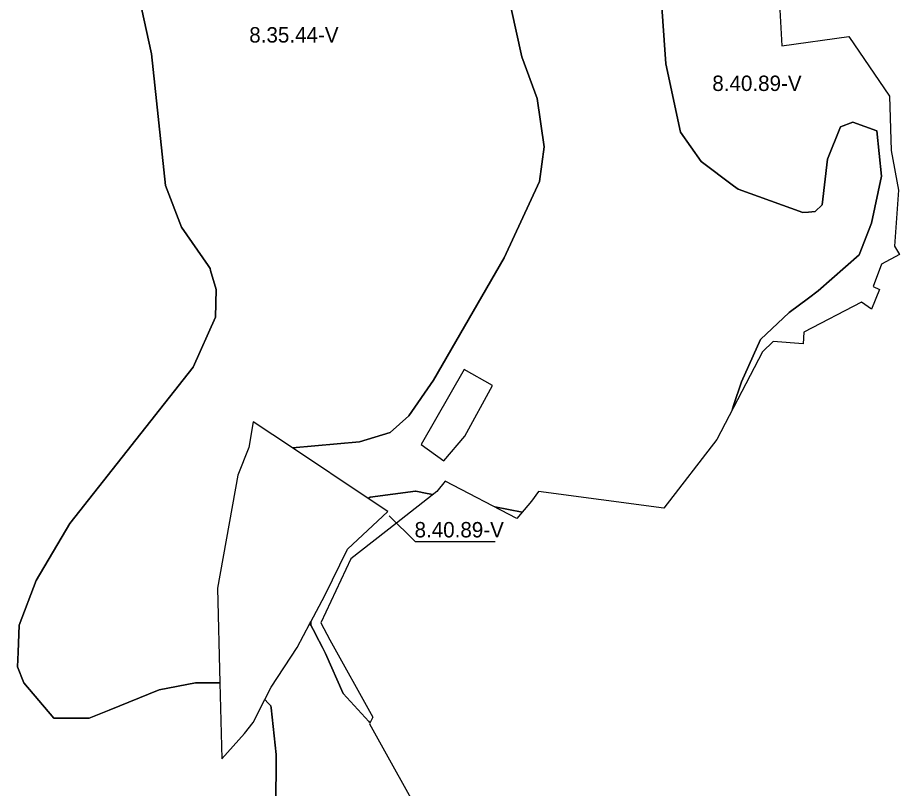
# Model space of a CAD drawing. Extents: x -547623 to -533936, y -1096714 to -1086523.
# Drawn here: x -544544 to -543971, y -1095788 to -1095288 of the extents above; entities that cross this region are included whole.
import ezdxf

# ---------------------------------------------------------------- set-up
doc = ezdxf.new("R2010")
doc.units = 0
doc.layers.add('Vrstva 27', color=7, linetype='Continuous')
doc.layers.add('Vrstva 28', color=7, linetype='Continuous')

msp = doc.modelspace()

# ---------------------------------------------------------------- linework, layer by layer
at = {"layer": 'Vrstva 27'}
msp.add_lwpolyline([(-544302.77, -1095610.93), (-544285.93, -1095627.77), (-544233.93, -1095627.77)], dxfattribs=at)
at = {"layer": 'Vrstva 28'}
for p, q in [((-544128, -1095246), (-544123, -1095317.5)), ((-544123, -1095317.5), (-544128, -1095246)), ((-544468, -1095261.5), (-544457, -1095311)), ((-544457, -1095311), (-544468, -1095261.5)), ((-544223.5, -1095281.5), (-544216.5, -1095313)), ((-544216.5, -1095313), (-544223.5, -1095281.5)), ((-544457, -1095311), (-544448, -1095396.5)), ((-544448, -1095396.5), (-544457, -1095311)), ((-544216.5, -1095313), (-544206.5, -1095340)), ((-544206.5, -1095340), (-544216.5, -1095313)), ((-544123, -1095317.5), (-544113.5, -1095362)), ((-544113.5, -1095362), (-544123, -1095317.5)), ((-544206.5, -1095340), (-544202, -1095371.5)), ((-544202, -1095371.5), (-544206.5, -1095340)), ((-544018, -1095379.5), (-544009.5, -1095358.5)), ((-544009.5, -1095358.5), (-544018, -1095379.5)), ((-544009.5, -1095358.5), (-544001.5, -1095355.5)), ((-544001.5, -1095355.5), (-544009.5, -1095358.5)), ((-544001.5, -1095355.5), (-543986, -1095361)), ((-543986, -1095361), (-544001.5, -1095355.5)), ((-543986, -1095361), (-543983, -1095390.5)), ((-543983, -1095390.5), (-543986, -1095361)), ((-544113.5, -1095362), (-544100, -1095381)), ((-544100, -1095381), (-544113.5, -1095362)), ((-544202, -1095371.5), (-544205, -1095394)), ((-544205, -1095394), (-544202, -1095371.5)), ((-544100, -1095381), (-544079.02, -1095396.73)), ((-544079.02, -1095396.73), (-544100, -1095381)), ((-544021.5, -1095409), (-544018, -1095379.5)), ((-544018, -1095379.5), (-544021.5, -1095409)), ((-544205, -1095394), (-544228, -1095443.5)), ((-544228, -1095443.5), (-544205, -1095394)), ((-543983, -1095390.5), (-543989.5, -1095421)), ((-543989.5, -1095421), (-543983, -1095390.5)), ((-544448, -1095396.5), (-544437.5, -1095423.5)), ((-544437.5, -1095423.5), (-544448, -1095396.5)), ((-544079.02, -1095396.73), (-544076, -1095399)), ((-544076, -1095399), (-544079.02, -1095396.73)), ((-544076, -1095399), (-544034, -1095414)), ((-544034, -1095414), (-544076, -1095399)), ((-544026, -1095413.5), (-544021.5, -1095409)), ((-544021.5, -1095409), (-544026, -1095413.5)), ((-544034, -1095414), (-544030.47, -1095413.78)), ((-544030.47, -1095413.78), (-544034, -1095414)), ((-544030.47, -1095413.78), (-544026, -1095413.5)), ((-544026, -1095413.5), (-544030.47, -1095413.78)), ((-544437.5, -1095423.5), (-544420.35, -1095448.53)), ((-544420.35, -1095448.53), (-544437.5, -1095423.5)), ((-543989.5, -1095421), (-543997.5, -1095441.5)), ((-543997.5, -1095441.5), (-543989.5, -1095421)), ((-544228, -1095443.5), (-544274, -1095523)), ((-544274, -1095523), (-544228, -1095443.5)), ((-543997.5, -1095441.5), (-544024, -1095465)), ((-544024, -1095465), (-543997.5, -1095441.5)), ((-544420.35, -1095448.53), (-544419, -1095450.5)), ((-544419, -1095450.5), (-544420.35, -1095448.53)), ((-544419, -1095450.5), (-544418.64, -1095451.72)), ((-544418.64, -1095451.72), (-544419, -1095450.5)), ((-544418.64, -1095451.72), (-544415, -1095464)), ((-544415, -1095464), (-544418.64, -1095451.72)), ((-544415, -1095464), (-544415.5, -1095482)), ((-544415.5, -1095482), (-544415, -1095464)), ((-544030.47, -1095469.77), (-544043, -1095479)), ((-544043, -1095479), (-544030.47, -1095469.77)), ((-544024, -1095465), (-544030.47, -1095469.77)), ((-544030.47, -1095469.77), (-544024, -1095465)), ((-544043, -1095479), (-544061.5, -1095496.5)), ((-544061.5, -1095496.5), (-544043, -1095479)), ((-544415.5, -1095482), (-544430, -1095514.5)), ((-544430, -1095514.5), (-544415.5, -1095482)), ((-544061.5, -1095496.5), (-544074, -1095524)), ((-544074, -1095524), (-544061.5, -1095496.5)), ((-544430, -1095514.5), (-544510, -1095616)), ((-544510, -1095616), (-544430, -1095514.5)), ((-544274, -1095523), (-544290, -1095546)), ((-544290, -1095546), (-544274, -1095523)), ((-544074, -1095524), (-544079.02, -1095539.28)), ((-544079.02, -1095539.28), (-544074, -1095524)), ((-544079.02, -1095539.28), (-544080.03, -1095542.35)), ((-544080.03, -1095542.35), (-544079.02, -1095539.28)), ((-544080.03, -1095542.35), (-544080.03, -1095542.35)), ((-544080.03, -1095542.35), (-544080.03, -1095542.35)), ((-544290, -1095546), (-544302, -1095557)), ((-544302, -1095557), (-544290, -1095546)), ((-544302, -1095557), (-544322, -1095563)), ((-544322, -1095563), (-544302, -1095557)), ((-544322, -1095563), (-544365.6, -1095566.9)), ((-544365.6, -1095566.9), (-544322, -1095563)), ((-544365.6, -1095566.9), (-544365.6, -1095566.9)), ((-544365.6, -1095566.9), (-544365.6, -1095566.9)), ((-544285.69, -1095595.02), (-544315, -1095599)), ((-544315, -1095599), (-544285.69, -1095595.02)), ((-544285.5, -1095595), (-544285.69, -1095595.02)), ((-544285.69, -1095595.02), (-544285.5, -1095595)), ((-544278.04, -1095596.48), (-544285.5, -1095595)), ((-544285.5, -1095595), (-544278.04, -1095596.48)), ((-544316.32, -1095599.68), (-544316.33, -1095599.68)), ((-544316.33, -1095599.68), (-544316.32, -1095599.68)), ((-544315, -1095599), (-544316.32, -1095599.68)), ((-544316.32, -1095599.68), (-544315, -1095599)), ((-544274.31, -1095597.23), (-544278.04, -1095596.48)), ((-544278.04, -1095596.48), (-544274.31, -1095597.23)), ((-544274.31, -1095597.23), (-544274.31, -1095597.23)), ((-544274.31, -1095597.23), (-544274.31, -1095597.23)), ((-544216.41, -1095608.74), (-544234.07, -1095605.23)), ((-544234.07, -1095605.23), (-544216.41, -1095608.74)), ((-544234.07, -1095605.23), (-544234.07, -1095605.23)), ((-544234.07, -1095605.23), (-544234.07, -1095605.23)), ((-544216.41, -1095608.74), (-544216.41, -1095608.74)), ((-544216.41, -1095608.74), (-544216.41, -1095608.74)), ((-544510, -1095616), (-544532, -1095653)), ((-544532, -1095653), (-544510, -1095616)), ((-544532, -1095653), (-544543, -1095682)), ((-544543, -1095682), (-544532, -1095653)), ((-544354.2, -1095680.99), (-544353.5, -1095682)), ((-544353.5, -1095682), (-544354.2, -1095680.99)), ((-544353.59, -1095679.84), (-544353.5, -1095682)), ((-544353.5, -1095682), (-544353.59, -1095679.84)), ((-544543, -1095682), (-544543.65, -1095699.52)), ((-544543.65, -1095699.52), (-544543, -1095682)), ((-544353.5, -1095682), (-544352.01, -1095684.91)), ((-544352.01, -1095684.91), (-544353.5, -1095682)), ((-544352.01, -1095684.91), (-544351.88, -1095685.16)), ((-544351.88, -1095685.16), (-544352.01, -1095684.91)), ((-544351.88, -1095685.16), (-544350.53, -1095687.79)), ((-544350.53, -1095687.79), (-544351.88, -1095685.16)), ((-544350.53, -1095687.79), (-544345.99, -1095696.62)), ((-544345.99, -1095696.62), (-544350.53, -1095687.79)), ((-544345.99, -1095696.62), (-544344, -1095700.5)), ((-544344, -1095700.5), (-544345.99, -1095696.62)), ((-544543.65, -1095699.52), (-544544, -1095709)), ((-544544, -1095709), (-544543.65, -1095699.52)), ((-544344, -1095700.5), (-544332.5, -1095726.5)), ((-544332.5, -1095726.5), (-544344, -1095700.5)), ((-544544, -1095709), (-544540, -1095719.5)), ((-544540, -1095719.5), (-544544, -1095709)), ((-544540, -1095719.5), (-544520.5, -1095742.5)), ((-544520.5, -1095742.5), (-544540, -1095719.5)), ((-544452, -1095724), (-544428.5, -1095719.5)), ((-544428.5, -1095719.5), (-544452, -1095724)), ((-544428.5, -1095719.5), (-544418.73, -1095719.5)), ((-544418.73, -1095719.5), (-544428.5, -1095719.5)), ((-544418.73, -1095719.5), (-544412.68, -1095719.5)), ((-544412.68, -1095719.5), (-544418.73, -1095719.5)), ((-544484.65, -1095737.27), (-544452, -1095724)), ((-544452, -1095724), (-544484.65, -1095737.27)), ((-544332.5, -1095726.5), (-544316, -1095744.5)), ((-544316, -1095744.5), (-544332.5, -1095726.5)), ((-544383.41, -1095730.33), (-544381.22, -1095732.66)), ((-544381.22, -1095732.66), (-544383.41, -1095730.33)), ((-544381.22, -1095732.66), (-544379.5, -1095734.5)), ((-544379.5, -1095734.5), (-544381.22, -1095732.66)), ((-544497.5, -1095742.5), (-544484.65, -1095737.27)), ((-544484.65, -1095737.27), (-544497.5, -1095742.5)), ((-544379.5, -1095734.5), (-544379.38, -1095735.61)), ((-544379.38, -1095735.61), (-544379.5, -1095734.5)), ((-544379.38, -1095735.61), (-544376, -1095766)), ((-544376, -1095766), (-544379.38, -1095735.61)), ((-544520.5, -1095742.5), (-544497.5, -1095742.5)), ((-544497.5, -1095742.5), (-544520.5, -1095742.5)), ((-544316, -1095744.5), (-544315.12, -1095745.28)), ((-544315.12, -1095745.28), (-544316, -1095744.5)), ((-544376, -1095766), (-544376.5, -1095811)), ((-544376.5, -1095811), (-544376, -1095766))]:
    msp.add_line(p, q, dxfattribs=at)
for points in [[(-544468, -1095261.5), (-544457, -1095311), (-544448, -1095396.5), (-544437.5, -1095423.5), (-544420.35, -1095448.53), (-544419, -1095450.5), (-544418.64, -1095451.72), (-544415, -1095464), (-544415.5, -1095482), (-544430, -1095514.5), (-544510, -1095616), (-544532, -1095653), (-544543, -1095682), (-544543.65, -1095699.52), (-544544, -1095709), (-544540, -1095719.5), (-544520.5, -1095742.5), (-544497.5, -1095742.5), (-544484.65, -1095737.27), (-544452, -1095724), (-544428.5, -1095719.5), (-544418.73, -1095719.5), (-544412.68, -1095719.5)], [(-544049.54, -1095270.54), (-544047.63, -1095305.89), (-544004.28, -1095299.75), (-543977.88, -1095338.42), (-543976.66, -1095373.81), (-543971.96, -1095399.59), (-543974.43, -1095436.02), (-543971.37, -1095441.38), (-543983.01, -1095447.56), (-543988.35, -1095462.07), (-543984.36, -1095464.15), (-543989.38, -1095476.78), (-543995.92, -1095472.19), (-544033.46, -1095491.87), (-544033.91, -1095499.36), (-544053.3, -1095497.79), (-544060.2, -1095504.49), (-544089.99, -1095561.36), (-544124.42, -1095605.98), (-544205.67, -1095595.15), (-544210.18, -1095601.48), (-544219.78, -1095612.68), (-544266.27, -1095588.44), (-544271.79, -1095595.25), (-544297.95, -1095615.75)], [(-544365.6, -1095566.9), (-544365.6, -1095566.9), (-544322, -1095563), (-544302, -1095557), (-544290, -1095546), (-544274, -1095523), (-544228, -1095443.5), (-544205, -1095394), (-544202, -1095371.5), (-544206.5, -1095340), (-544216.5, -1095313), (-544223.5, -1095281.5)], [(-544235.7, -1095526.48), (-544253.92, -1095516.11), (-544281.99, -1095564.8), (-544267.2, -1095575.31), (-544253.66, -1095559.21), (-544235.7, -1095526.48)], [(-544412.68, -1095719.5), (-544411.45, -1095768.8), (-544396.62, -1095752.39), (-544391.02, -1095745.18), (-544383.41, -1095730.33), (-544379.25, -1095722.21), (-544362.42, -1095696.47), (-544354.2, -1095680.99), (-544353.59, -1095679.84), (-544353.59, -1095679.84), (-544344.47, -1095662.66), (-544329.83, -1095632.77), (-544303.59, -1095608.15), (-544316.33, -1095599.68), (-544365.6, -1095566.9), (-544390.96, -1095550.03), (-544393.91, -1095566.59), (-544400.96, -1095584.54), (-544414.21, -1095657.95), (-544412.68, -1095719.5)], [(-544297.95, -1095615.75), (-544327.51, -1095638.93), (-544346.99, -1095680.46), (-544341.34, -1095691.5), (-544313.23, -1095741.77), (-544315.54, -1095746.06), (-544277.8, -1095813.87)], [(-544353.59, -1095679.84), (-544354.2, -1095680.99)], [(-544354.2, -1095680.99), (-544353.5, -1095682), (-544353.59, -1095679.84)], [(-544315.12, -1095745.28), (-544316, -1095744.5), (-544332.5, -1095726.5), (-544344, -1095700.5), (-544345.99, -1095696.62), (-544350.53, -1095687.79), (-544351.88, -1095685.16), (-544352.01, -1095684.91), (-544353.5, -1095682), (-544354.2, -1095680.99)], [(-544383.41, -1095730.33), (-544381.22, -1095732.66), (-544379.5, -1095734.5), (-544379.38, -1095735.61), (-544376, -1095766), (-544376.5, -1095811)]]:
    msp.add_lwpolyline(points, dxfattribs=at)

# ---------------------------------------------------------------- texts
at = {"layer": 'Vrstva 27'}
for s, p in [('8.35.44-V', (-544393.57, -1095303.69)), ('8.40.89-V', (-544092.85, -1095335.15)), ('8.40.89-V', (-544286.22, -1095625.05))]:
    msp.add_text(s, height=10, dxfattribs=at).set_placement(p)

doc.saveas('drawing.dxf')
